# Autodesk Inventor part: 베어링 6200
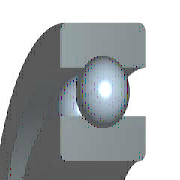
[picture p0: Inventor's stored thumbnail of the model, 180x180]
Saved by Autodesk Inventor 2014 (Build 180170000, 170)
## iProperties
Created: 2012-02
Part Number: 베어링 6200
Material: 강철, 연강
Description: 깊은 그루브 볼 베어링
Document SubType Name: Modeling
Standard: KS B 2023
Designer: mduedu
Standards Organization: KS
Language: ko-KR
Size Designation: 6200 - 10 x 30 x 9
Categories: <MemberInstance><Categories><Category DisplayName="샤프트 부품" InternalName="7f7aeb1f-a693-4053-b835-cee3144e0d98" Mnemonic="SHFT"><Category DisplayName="베어링" Inter
Density: 1 g/cm^3
Appearance: Yellow
IsCustomPart: 1
Author: mduedu
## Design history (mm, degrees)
sketch "스케치" dims "d0" = 5.2 (= -0.26 x WD + 0.26 x BD)
  geometry: L1 (1.9, 10)-(7.1, 10); L2 (4.5, 10)-(4.5, 7.4); L3 (4.5, 10)-(4.5, 12.6); L4 (2.568, 8.26)-(0, 8.26); L5 (0, 5)-(9, 5); L6 (2.568, 11.74)-(0, 11.74); L7 (0, 15)-(9, 15); L8 (9, 5)-(9, 8.26); L9 (6.432, 8.26)-(9, 8.26); L10 (6.432, 11.74)-(9, 11.74); L11 (9, 15)-(9, 11.74); L12 (-1.4, 0)-(8.4, 0) reference; L13 (0, -0.3)-(0, 5.3) reference
  constraints: 22 end point, 4 point on line, 2 collinear, 2 perpendicular, 2 symmetric about line, 1 midpoint, 1 parallel, 14 other
  dimensions: "d9" = 10 diameter of L5 L12 (= WD); "d11" = 30 diameter of L7 L12 (= BD); "d12" = 9 distance between parallel lines of L8 L13 (= KB); "d13" = 16.52 diameter of L9 L12 (= 0.326 x BD + 0.674 x WD)
revolve "본체" stored, may be unused: angle "d6" = 90 deg
revolve "볼" stored, may be unused: angle "d7" = 90 deg
pattern_circular "IDS_ARRAYBALL[SIMPL:T]" dims angle "d3" = 360 deg
body "Solid1"
fillet "모깎기1" dims "d1" = 0.6 (= KRS)
other parameters: "WD" = 10 [user parameter; used in 5 equation terms], "BD" = 30 [user parameter; used in 5 equation terms], "KB" = 9 [user parameter; used in 1 equation term], "KRS" = 0.6 [user parameter; used in 1 equation term], "d4" = 0, "d5" = 0, "d8" = 0, "d14" = 0, "d15" = 0, "BBA" = 0 [user parameter], "BC0" = 2360000 [user parameter], "BC" = 5070000 [user parameter], "BR" = 15 (= 0.5 x BD) [user parameter], "WR" = 5 (= 0.5 x WD) [user parameter]
